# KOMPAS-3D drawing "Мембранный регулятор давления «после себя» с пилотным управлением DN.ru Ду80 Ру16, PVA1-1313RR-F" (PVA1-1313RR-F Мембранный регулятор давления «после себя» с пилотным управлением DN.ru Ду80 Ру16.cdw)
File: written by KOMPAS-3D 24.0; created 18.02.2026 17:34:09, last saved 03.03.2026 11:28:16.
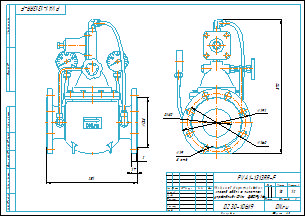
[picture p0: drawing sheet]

Document properties: art: D230-10619; Автор: R2D2; Форматы листов документа: A3; Полное имя файла: PVA1-1313RR-F Мембранный регулятор давления «после себя» с пилотным управлением DN.ru Ду80 Ру16.m3d; Масса: 13; Наименование: Мембранный регулятор давления «после себя» с пилотным управлением DN.ru Ду80 Ру16; Количество листов документа: 1; Примечание: D230-10619

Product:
- Part/product: Мембранный регулятор давления «после себя» с пилотным управлением DN.ru Ду80 Ру16  | designation PVA1-1313RR-F
    Масса: 13
    Раздел спецификации: Прочие изделия
    Примечание: D230-10619
    additional columns: D230-10619

Views: Вид 1, Спереди
Referenced files in E:\Работа\Зайцев\PVA1-1313RR-F Мембранный регулятор давления «после себя» с пилотным управлением DN.ru Ду50-200 Ру16\DN80\: PVA1-1313RR-F Мембранный регулятор давления «после себя» с пилотным управлением DN.ru Ду80 Ру16.m3d
Referenced files in E:\Работа\Зайцев\Для компаса\: чертеж DN.ru А3.cdt
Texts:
  Линейный размер
  PVA1-1313RR-F
  чертеж DN.ru А3.cdt
  Мембранный регулятор давления
  «после себя» с пилотным
  управлением DN.ru Ду80 Ру16
  prop
  Мембранный регулятор давления «после себя» с пилотным управлением DN.ru Ду80 Ру16
  PVA1-1313RR-F Мембранный регулятор давления «после себя» с пилотным управлением DN.ru Ду80 Ру16
Dimensions and other numbers on the sheet: 0; 3; 2; 4; 251; 17; 138; 1:2; 1; 13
